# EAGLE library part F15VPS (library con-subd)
SUB-D
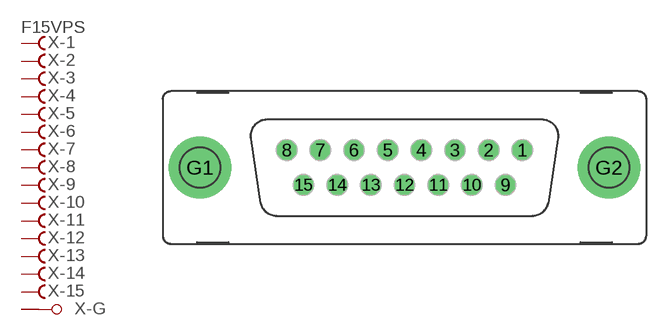
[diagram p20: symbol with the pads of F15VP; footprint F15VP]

Designator prefix X; gates -2=F -3=F -4=F -5=F -6=F -7=F -8=F -9=F -10=F -11=F -12=F -13=F -14=F -15=F -G=GND -1=FV

## F15VPS (OC_FARNELL: unknown; OC_NEWARK: unknown)  [F15VP]
1  -1:F  pas
2  -2:F  pas
3  -3:F  pas
4  -4:F  pas
5  -5:F  pas
6  -6:F  pas
7  -7:F  pas
8  -8:F  pas
9  -9:F  pas
10  -10:F  pas
11  -11:F  pas
12  -12:F  pas
13  -13:F  pas
14  -14:F  pas
15  -15:F  pas
G1  -G:G1  pas
G2  -G:G2  pas

## Footprint F15VP (pad centres in mm)
SUB-D
drill 1.016 octagon: 1 9.601,1.422; 2 6.858,1.422; 3 4.115,1.422; 4 1.372,1.422; 5 -1.372,1.422; 6 -4.115,1.422; 7 -6.858,1.422; 8 -9.601,1.422; 9 8.23,-1.422; 10 5.486,-1.422; 11 2.743,-1.422; 12 0,-1.422; 13 -2.743,-1.422; 14 -5.486,-1.422; 15 -8.23,-1.422
drill 3.302 pad 5.08 round: G1 -16.662,0; G2 16.662,0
